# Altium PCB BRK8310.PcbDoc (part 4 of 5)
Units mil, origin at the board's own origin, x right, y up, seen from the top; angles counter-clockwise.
Board outline 6600.39 x 4492.13 mil, 4 copper layers (L1-Top, L2-GND, L3-GND, L4-BOT), stack 60.25 mil thick; 119 components, 266 nets, 1026 pads, 596 vias.
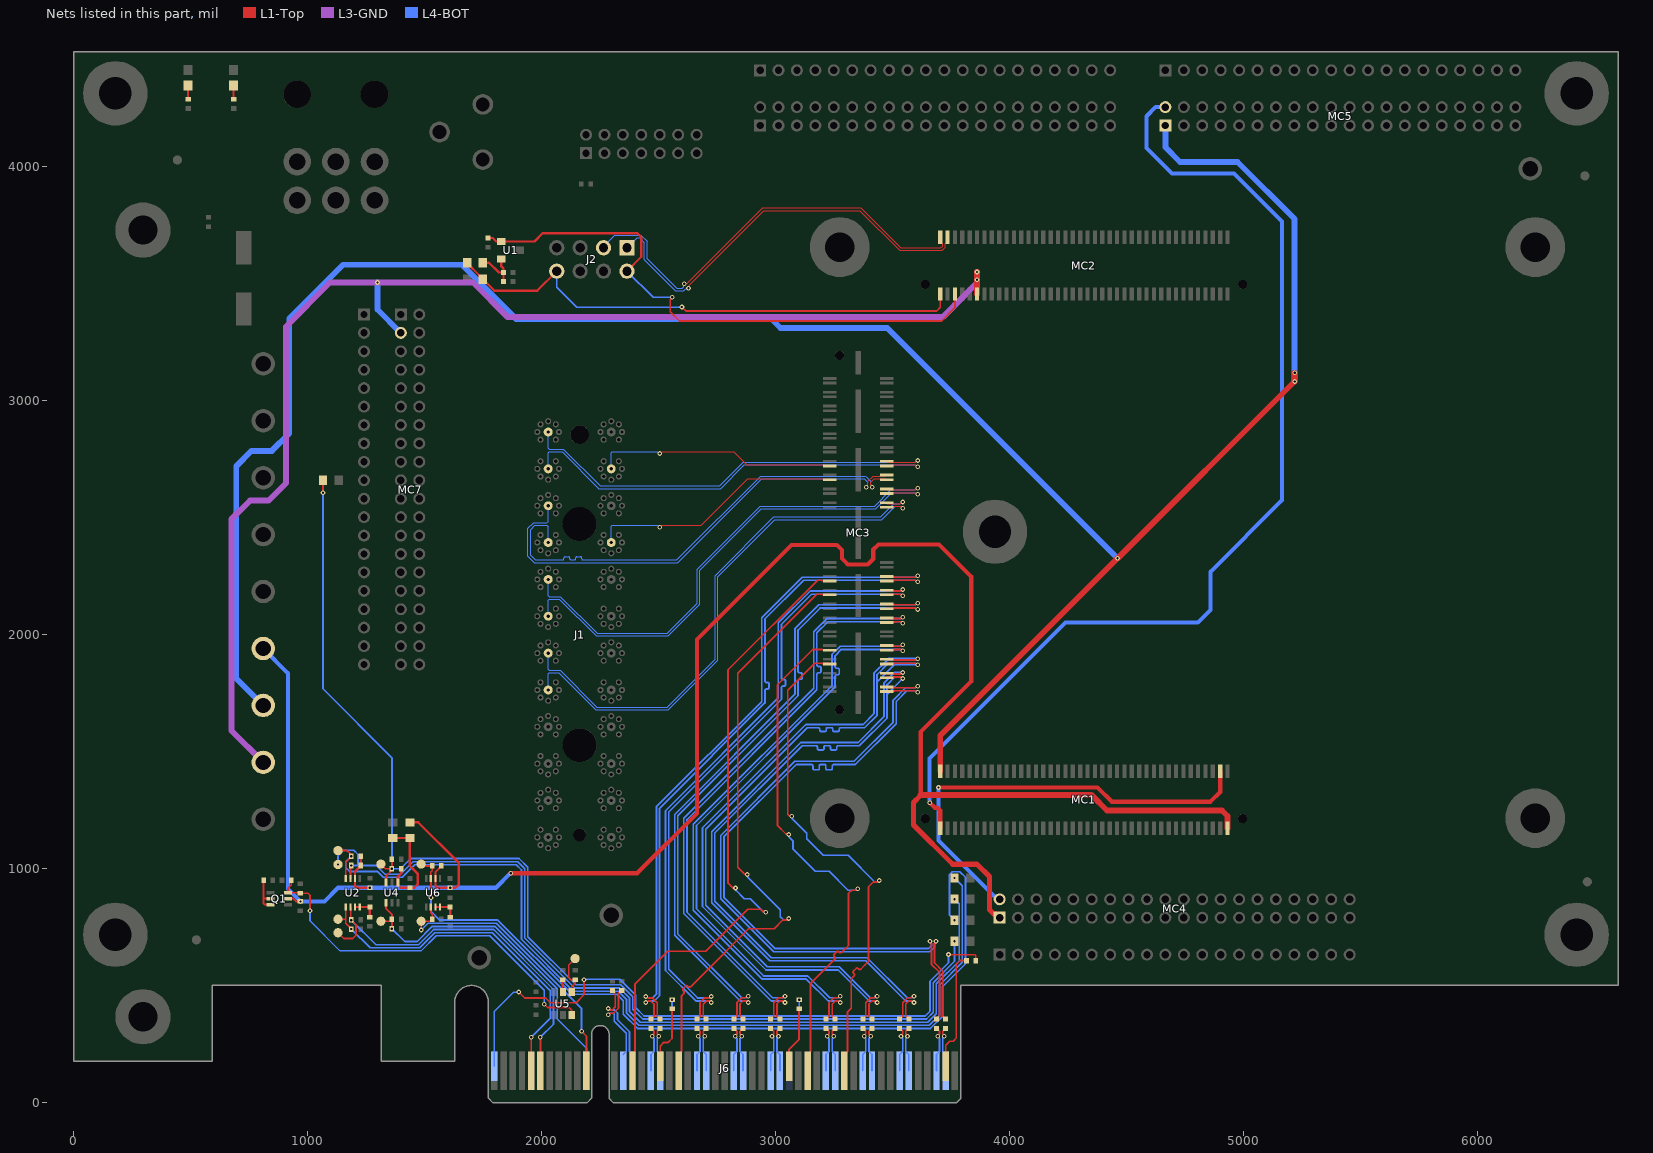
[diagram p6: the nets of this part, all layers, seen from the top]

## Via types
v1: diameter 20, hole 10, L1-Top to L4-BOT, tented both sides, 596 vias

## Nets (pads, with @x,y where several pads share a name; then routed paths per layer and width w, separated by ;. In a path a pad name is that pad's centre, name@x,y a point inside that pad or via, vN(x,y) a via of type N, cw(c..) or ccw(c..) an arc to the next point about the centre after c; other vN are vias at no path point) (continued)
MGT_RXP2_224: J6.B37 MC3.9 | length 2198.9
  L1-Top w7.5: v1(3068.1,1225.01) 3065.71,1227.41 3056.87,1227.41 3051.27,1233 3051.27,1764.37 3165.98,1879.08 3196.93,1879.08 3198.41,1877.6 3229.08,1877.6 MC3.9@3230.7,1875.98 ; J6.B37@3293.3,137.79 3293.3,206.69 3306.23,219.63 3306.23,240.7 3306.23,386.89 3323.12,403.78 3323.12,531.3 3331.45,539.62 3334.1,542.27 ccw(c3328.79,547.57) 3334.1,552.88 3331.89,555.08 cw(c3335.78,558.97) 3331.89,562.86 3343.56,574.53 cw(c3347.45,570.64) 3351.34,574.53 3353.54,572.32 ccw(c3358.85,577.62) 3364.15,572.32 3381.47,589.64 3396.44,604.61 3396.44,923.38 3417.16,944.1 3433.27,944.1 3439.52,950.35 v1(3442.91,950.35)
  L4-BOT w7.5: v1(3068.1,1225.01) 3070.49,1222.62 3070.49,1213.78 3132.67,1151.6 3132.67,1129.07 3203.66,1058.09 3309.84,1058.09 3423.83,944.1 3433.27,944.1 3439.52,950.35 v1(3442.91,950.35)
MGT_RXP2_225: J6.B19 MC3.29 | length 2643.1
  L1-Top w7.5: J6.B19@2584.64,137.79 2584.64,206.69 2597.57,219.63 2597.57,240.7 2597.57,458.1 2603.69,464.22 2606.35,466.87 ccw(c2601.04,472.17) 2606.35,477.48 2603.69,480.14 cw(c2607.57,484.03) 2603.69,487.92 2615.35,499.58 cw(c2619.24,495.69) 2623.13,499.58 2625.79,496.92 ccw(c2631.1,502.23) 2636.4,496.92 2687.36,547.88 2883.68,744.21 2992.94,744.21 3030.52,781.79 3050.72,781.79 3055.11,786.19 v1(3055.11,788.04) ; v1(2877.83,976.14) 2875.44,978.54 2866.6,978.54 2865.46,979.68 2837.44,1007.69 2837.44,1836.85 3174.94,2174.35 3196.93,2174.35 3198.41,2172.88 3229.08,2172.88 MC3.29@3230.7,2171.26
  L4-BOT w7.5: v1(2877.83,976.14) 2880.22,973.75 2880.22,964.91 3019.5,825.64 3019.5,796.16 3033.86,781.79 3045.48,781.79 3051.73,788.04 v1(3055.11,788.04)
MGT_RXP2_226: J1.B09 MC3.49 | length 1095
  L1-Top w5.25: v1(2504.63,2460.52) 2507.71,2460.52 2515.08,2467.89 2680.63,2467.89 2880.34,2667.6 3201.71,2667.6 3202.64,2666.66 3227.42,2666.66 MC3.49@3230.7,2663.38
  L4-BOT w5.25: J1.B09@2296.96,2394.78 2296.96,2463.74 2301.11,2467.89 2420.93,2467.89 2494.18,2467.89 2501.56,2460.52 v1(2504.63,2460.52)
MGT_RXP3_224: J6.B33 MC3.13 | length 2274
  L1-Top w7.5: v1(3055.22,1146.98) 3052.82,1149.38 3043.99,1149.38 3007.08,1186.28 3007.08,1785.87 3159.33,1938.13 3196.93,1938.13 3198.41,1936.66 3229.08,1936.66 MC3.13@3230.7,1935.04 ; J6.B33@3135.82,137.79 3135.82,206.69 3148.75,219.63 3148.75,510.61 3249.16,611.02 3251.81,613.67 ccw(c3246.51,618.97) 3251.81,624.27 3249.15,626.94 cw(c3253.04,630.82) 3249.15,634.71 3260.82,646.38 cw(c3264.71,642.49) 3268.59,646.38 3271.26,643.72 ccw(c3276.56,649.02) 3281.86,643.72 3297.2,659.06 3311.02,672.87 3311.02,895.49 3324.69,909.17 3344.41,909.17 3350.39,915.15 v1(3350.39,915.42)
  L4-BOT w7.5: v1(3055.22,1146.98) 3057.61,1144.59 3057.61,1135.75 3073.29,1120.07 3073.29,1085.56 3169.1,989.75 3228.25,989.75 3308.83,909.17 3340.75,909.17 3347,915.42 v1(3350.39,915.42)
MGT_RXP3_225: J6.B14 MC3.33 | length 2795.5
  L1-Top w7.5: J6.B14@2387.79,137.79 2387.79,206.69 2398.91,217.81 2398.91,508.47 2538.58,648.14 2700.54,648.14 2880.48,828.08 2935.88,828.08 2946.43,817.53 2955.27,817.53 v1(2957.66,815.14) ; v1(2828.19,918.18) 2827.8,917.79 2818.89,917.79 2795.42,941.26 2795.42,1849.99 3178.84,2233.41 3196.93,2233.41 3198.41,2231.93 3229.08,2231.93 MC3.33@3230.7,2230.31
  L4-BOT w7.5: v1(2828.19,918.18) 2830.58,915.79 2830.58,907.61 2865.42,872.76 2891.19,872.76 2946.43,817.53 2955.27,817.53 v1(2957.66,815.14)
MGT_RXP3_226: J1.B11 MC3.53 | length 1035.6
  L1-Top w5.25: v1(2504.63,2775.48) 2507.71,2775.48 2515.08,2782.85 2820.78,2782.85 2876.97,2726.66 3201.71,2726.66 3202.64,2725.72 3227.42,2725.72 MC3.53@3230.7,2722.44
  L4-BOT w5.25: J1.B11@2296.96,2709.74 2296.96,2778.7 2301.11,2782.85 2420.93,2782.85 2494.18,2782.85 2501.56,2775.48 v1(2504.63,2775.48)
MGT_TXN0_224: C30.2 MC3.4 | length 2965.2
  L1-Top w7.5: MC3.4@3474.01,1777.56 3476.16,1775.4 3506.84,1775.4 3507.77,1774.47 3596.66,1774.47 3602.91,1780.72 v1(3606.29,1780.72) ; v1(3685.1,690.4) 3685.1,687.02 3678.85,680.77 3678.85,597.93 3713.44,563.35 3713.44,369.54 3717.83,365.15 3720.28,365.15 C30.2@3726.37,359.05
  L4-BOT w7.5: v1(3606.29,1780.72) 3602.91,1780.72 3596.66,1774.47 3554.58,1774.47 3501.34,1721.23 3501.34,1626.46 3334.53,1459.65 3081.8,1459.65 2765,1142.84 2765,872.82 2991.87,645.95 3658.42,645.95 3678.85,666.38 3678.85,680.77 3685.1,687.02 v1(3685.1,690.4)
MGT_TXN0_225: C20.2 MC3.24 | length 2617.4
  L1-Top w7.5: C20.2@3017.71,359.05 3011.22,365.54 3009.17,365.54 3004.77,369.93 3004.77,386.56 3004.77,422.67 3017.54,435.43 3029.73,435.43 3035.98,429.18 v1(3039.36,429.18) ; MC3.24@3474.01,2072.83 3476.16,2070.68 3506.84,2070.68 3507.77,2069.74 3533.67,2069.74 3539.92,2075.99 v1(3543.3,2075.99)
  L4-BOT w7.5: v1(3039.36,429.18) 3035.98,429.18 3029.73,435.43 2980.67,435.43 2606.93,809.17 2606.93,1216.44 3162.18,1771.68 3162.18,2014.26 3217.65,2069.74 3533.67,2069.74 3539.92,2075.99 v1(3543.3,2075.99)
MGT_TXN0_226: J1.A06 MC3.44 | length 2298.2
  L1-Top w5.25: MC3.44@3474.01,2564.96 3477.29,2561.68 3502.06,2561.68 3503,2560.74 3512.13,2560.74 3532.85,2560.74 3540.22,2568.12 v1(3543.3,2568.12)
  L4-BOT w5.25: J1.A06@2027.27,1922.33 2027.27,1853.37 2031.42,1849.22 2077.99,1849.22 2235.64,1691.58 2535.78,1691.58 2610.71,1766.51 2740.74,1896.54 2740.74,2253.42 2991.69,2504.37 3448.81,2504.37 3505.18,2560.74 3532.85,2560.74 3540.22,2568.12 v1(3543.3,2568.12)
MGT_TXN1_224: C26.2 MC3.8 | length 2753.4
  L1-Top w7.5: MC3.8@3474.01,1836.61 3476.16,1834.46 3506.84,1834.46 3507.77,1833.52 3533.67,1833.52 3539.92,1839.77 v1(3543.3,1839.77) ; C26.2@3568.89,359.05 3562.4,365.54 3560.35,365.54 3555.95,369.93 3555.95,386.56 3555.95,422.67 3568.72,435.43 3580.91,435.43 3587.16,429.18 v1(3590.54,429.18)
  L4-BOT w7.5: v1(3543.3,1839.77) v1@3539.92,1839.77 ; v1(3590.54,429.18) 3587.16,429.18 3580.91,435.43 3555.96,435.43 3384.45,606.95 2974.62,606.95 2726,855.57 2726,1159 3107.36,1540.35 3352,1540.35 3462.34,1650.69 3462.34,1746.31 3462.34,1793.43 3502.43,1833.52 ; 3502.43,1833.52 3508.68,1839.77 v1@3539.92,1839.77 ; 3502.43,1833.52 3533.67,1833.52 v1@3539.92,1839.77
MGT_TXN1_225: C18.2 MC3.28 | length 2774.3
  L1-Top w7.5: C18.2@2860.23,359.05 2853.74,365.54 2851.69,365.54 2847.29,369.93 2847.29,386.56 2847.29,422.67 2860.06,435.43 2872.25,435.43 2878.5,429.18 v1(2881.88,429.18) ; MC3.28@3474.01,2131.89 3476.16,2129.73 3506.84,2129.73 3507.77,2128.8 3596.66,2128.8 3602.91,2135.05 v1(3606.29,2135.05)
  L4-BOT w7.5: v1(2881.88,429.18) 2878.5,429.18 2872.25,435.43 2848.81,435.43 2567.93,716.31 2567.93,1232.59 3081.97,1746.63 3081.97,2026.83 3183.94,2128.8 3596.66,2128.8 3602.91,2135.05 v1(3606.29,2135.05)
MGT_TXN1_226: J1.A08 MC3.48 | length 2194
  L1-Top w5.25: MC3.48@3474.01,2624.01 3477.29,2620.73 3502.06,2620.73 3503,2619.8 3595.84,2619.8 3603.22,2627.17 v1(3606.29,2627.17)
  L4-BOT w5.25: J1.A08@2027.27,2237.3 2027.27,2168.33 2031.42,2164.18 2079.67,2164.18 2236.8,2007.04 2535.62,2007.04 2664.03,2135.45 2664.03,2281.07 2933.44,2550.48 3422.14,2550.48 3491.46,2619.8 3595.84,2619.8 3603.22,2627.17 v1(3606.29,2627.17)
MGT_TXN2_224: C24.2 MC3.12 | length 2950.7
  L1-Top w7.5: C24.2@3411.41,359.05 3404.92,365.54 3402.87,365.54 3398.47,369.93 3398.47,386.56 3398.47,422.67 3411.24,435.43 3423.43,435.43 3429.68,429.18 v1(3433.06,429.18) ; MC3.12@3474.01,1895.67 3476.16,1893.51 3506.84,1893.51 3507.77,1892.58 3596.66,1892.58 3602.91,1898.83 v1(3606.29,1898.83)
  L4-BOT w7.5: v1(3433.06,429.18) 3429.68,429.18 3423.43,435.43 3398.97,435.43 3266.45,567.95 2958.47,567.95 2687,839.41 2687,1175.15 3128.97,1617.13 3373.62,1617.13 3419.56,1663.07 3419.56,1800.22 3419.56,1836.3 3475.84,1892.58 ; v1(3606.29,1898.83) v1@3602.91,1898.83 ; 3475.84,1892.58 3482.09,1898.83 v1@3602.91,1898.83 ; 3475.84,1892.58 3596.66,1892.58 v1@3602.91,1898.83
MGT_TXN2_225: C16.2 MC3.32 | length 2714.7
  L1-Top w7.5: C16.2@2702.75,358.66 2696.26,365.15 2694.21,365.15 2689.81,369.54 2689.81,386.17 2689.81,422.28 2702.58,435.04 2714.77,435.04 2721.02,428.79 v1(2724.4,428.79) ; MC3.32@3474.01,2190.94 3476.16,2188.79 3506.84,2188.79 3507.77,2187.85 3533.67,2187.85 3539.92,2194.1 v1(3543.3,2194.1)
  L4-BOT w7.5: v1(2724.4,428.79) 2721.02,428.79 2714.77,435.04 2659.76,435.04 2528.93,565.87 2528.93,1248.75 3011.11,1730.92 3011.11,2051.57 3147.38,2187.85 3533.67,2187.85 3539.92,2194.1 v1(3543.3,2194.1)
MGT_TXN2_226: J1.A10 MC3.52 | length 2048.7
  L1-Top w5.25: v1(3386.58,2631) 3386.58,2634.05 3393.95,2641.42 3393.95,2656.39 3416.41,2678.85 3437.59,2678.85 3445.01,2678.85 3445.95,2679.79 3470.73,2679.79 MC3.52@3474.01,2683.07
  L4-BOT w5.25: J1.A10@2027.27,2552.26 2027.27,2484.39 2022.03,2479.14 1964.69,2479.14 1940.52,2454.97 1940.52,2336.14 1967.44,2309.22 2581.12,2309.22 2939.49,2667.6 3378.34,2667.6 3393.95,2651.99 3393.95,2641.45 3386.58,2634.07 v1(3386.58,2631)
MGT_TXN3_224: C22.2 MC3.16 | length 2635.8
  L1-Top w7.5: C22.2@3253.93,359.05 3247.44,365.54 3245.39,365.54 3240.99,369.93 3240.99,386.56 3240.99,422.67 3253.76,435.43 3265.95,435.43 3272.2,429.18 v1(3275.58,429.18) ; MC3.16@3474.01,1954.72 3476.16,1952.57 3506.84,1952.57 3507.77,1951.63 3533.67,1951.63 3539.92,1957.88 v1(3543.3,1957.88)
  L4-BOT w7.5: v1(3275.58,429.18) 3272.2,429.18 3265.95,435.43 3224.32,435.43 3130.8,528.95 2942.31,528.95 2647.63,823.63 2647.63,1190.94 3240.18,1783.48 3240.18,1916.7 3275.11,1951.63 3533.67,1951.63 3539.92,1957.88 v1(3543.3,1957.88)
MGT_TXN3_225: C14.2 MC3.36 | length 2861.5
  L1-Top w7.5: v1(2444.87,454.79) 2448.26,454.79 2453.01,450.04 2453.22,450.04 2454.72,448.54 2472.29,448.54 2492.96,427.87 2492.96,380.58 2492.96,369.54 2497.36,365.15 2499.41,365.15 C14.2@2505.9,358.66 ; MC3.36@3474.01,2250 3476.16,2247.84 3506.84,2247.84 3507.77,2246.91 3596.66,2246.91 3602.91,2253.16 v1(3606.29,2253.16)
  L4-BOT w7.5: v1(2444.87,454.79) 2448.26,454.79 2454.51,448.54 2474.12,448.54 2489.93,464.35 2489.93,1264.9 2940.24,1715.21 2940.24,2073.48 3113.67,2246.91 3128.94,2246.91 3596.66,2246.91 3602.91,2253.16 v1(3606.29,2253.16)
MGT_TXN3_226: J1.A12 MC3.56 | length 1897
  L1-Top w5.25: MC3.56@3474.01,2742.12 3477.29,2738.84 3502.06,2738.84 3503,2737.91 3595.84,2737.91 3603.22,2745.28 v1(3606.29,2745.28)
  L4-BOT w5.25: J1.A12@2027.27,2867.22 2027.27,2798.25 2031.42,2794.1 2091.32,2794.1 2248.79,2636.64 2760.25,2636.64 2861.52,2737.91 3595.84,2737.91 3603.22,2745.28 v1(3606.29,2745.28)
MGT_TXP0_224: C29.2 MC3.2 | length 2966.6
  L1-Top w7.5: MC3.2@3474.01,1757.87 3476.16,1760.03 3506.84,1760.03 3507.77,1760.97 3596.66,1760.97 3602.91,1754.72 v1(3606.29,1754.72) ; v1(3659.1,690.4) 3659.1,687.02 3665.35,680.77 3665.35,592.34 3699.94,557.76 3699.94,369.54 3695.54,365.15 3693.09,365.15 C29.2@3687,359.05
  L4-BOT w7.5: v1(3606.29,1754.72) 3602.91,1754.72 3596.66,1760.97 3560.17,1760.97 3514.84,1715.63 3514.84,1620.86 3340.12,1446.15 3283.46,1446.15 3248.83,1446.15 ccw(c3248.83,1438.65) 3241.33,1438.65 3241.33,1429.37 cw(c3235.83,1429.37) 3235.83,1423.87 3219.33,1423.87 cw(c3219.33,1429.37) 3213.83,1429.37 3213.83,1440.65 ccw(c3208.33,1440.65) 3208.33,1446.15 3191.83,1446.15 ccw(c3191.83,1440.65) 3186.33,1440.65 3186.33,1429.37 cw(c3180.83,1429.37) 3180.83,1423.87 3164.33,1423.87 cw(c3164.33,1429.37) 3158.83,1429.37 3158.83,1438.65 ccw(c3151.33,1438.65) 3151.33,1446.15 3120.08,1446.15 3087.39,1446.15 2778.5,1137.25 2778.5,878.41 2997.46,659.45 3652.83,659.45 3665.35,671.97 3665.35,680.77 3659.1,687.02 v1(3659.1,690.4)
MGT_TXP0_225: C19.2 MC3.22 | length 2618.3
  L1-Top w7.5: C19.2@2978.34,359.05 2984.82,365.54 2986.88,365.54 2991.27,369.93 2991.27,380.97 2991.27,428.26 3011.94,448.93 3029.52,448.93 3031.02,450.43 3031.23,450.43 3035.98,455.18 v1(3039.36,455.18) ; MC3.22@3474.01,2053.15 3476.16,2055.3 3506.84,2055.3 3507.77,2056.24 3533.67,2056.24 3539.92,2049.99 v1(3543.3,2049.99)
  L4-BOT w7.5: v1(3039.36,455.18) 3035.98,455.18 3029.73,448.93 2986.27,448.93 2620.43,814.76 2620.43,1210.85 3175.68,1766.09 3175.68,1799.21 3175.68,1830.46 cw(c3183.18,1830.46) 3183.18,1837.96 3187.41,1837.96 ccw(c3187.41,1843.46) 3192.91,1843.46 3192.91,1859.96 ccw(c3187.41,1859.96) 3187.41,1865.46 3183.18,1865.46 cw(c3183.18,1872.96) 3175.68,1872.96 3175.68,1905.51 3175.68,2008.67 3223.25,2056.24 3533.67,2056.24 3539.92,2049.99 v1(3543.3,2049.99)
MGT_TXP0_226: J1.A05 MC3.42 | length 2298.2
  L1-Top w5.25: MC3.42@3474.01,2545.27 3477.29,2548.55 3502.06,2548.55 3503,2549.49 3516.79,2549.49 3532.85,2549.49 3540.22,2542.12 v1(3543.3,2542.12)
  L4-BOT w5.25: J1.A05@2027.27,1764.85 2027.27,1833.82 2031.42,1837.97 2073.33,1837.97 2230.98,1680.33 2540.44,1680.33 2748.69,1888.59 2751.99,1891.88 2751.99,2248.76 2996.35,2493.12 3453.47,2493.12 3509.84,2549.49 3532.85,2549.49 3540.22,2542.12 v1(3543.3,2542.12)
MGT_TXP1_224: C25.2 MC3.6 | length 2838.8
  L1-Top w7.5: MC3.6@3474.01,1816.93 3476.16,1819.08 3506.84,1819.08 3507.77,1820.02 3533.67,1820.02 3539.92,1813.77 v1(3543.3,1813.77) ; C25.2@3529.52,359.05 3536.01,365.54 3538.06,365.54 3542.45,369.93 3542.45,380.97 3542.45,428.26 3563.13,448.93 3580.7,448.93 3582.2,450.43 3582.41,450.43 3587.16,455.18 v1(3590.54,455.18)
  L4-BOT w7.5: v1(3590.54,455.18) 3587.16,455.18 3580.91,448.93 3561.55,448.93 3390.04,620.45 2980.21,620.45 2739.5,861.16 2739.5,1153.41 3112.95,1526.85 3139.76,1526.85 3171.01,1526.85 cw(c3171.01,1519.35) 3178.51,1519.35 3178.51,1514.09 ccw(c3184.01,1514.09) 3184.01,1508.59 3200.51,1508.59 ccw(c3200.51,1514.09) 3206.01,1514.09 3206.01,1521.35 cw(c3211.51,1521.35) 3211.51,1526.85 3228.01,1526.85 cw(c3228.01,1521.35) 3233.51,1521.35 3233.51,1514.09 ccw(c3239.01,1514.09) 3239.01,1508.59 3255.51,1508.59 ccw(c3255.51,1514.09) 3261.01,1514.09 3261.01,1519.35 cw(c3268.51,1519.35) 3268.51,1526.85 3296.26,1526.85 3357.59,1526.85 3475.84,1645.1 3475.84,1746.31 ; 3475.84,1746.31 3475.84,1787.84 3508.02,1820.02 3533.67,1820.02 3539.92,1813.77 v1(3543.3,1813.77) 3475.84,1746.31
MGT_TXP1_225: C17.2 MC3.26 | length 2774.6
  L1-Top w7.5: C17.2@2820.86,359.05 2827.34,365.54 2829.4,365.54 2833.79,369.93 2833.79,380.97 2833.79,428.26 2854.46,448.93 2872.04,448.93 2873.54,450.43 2873.75,450.43 2878.5,455.18 v1(2881.88,455.18) ; MC3.26@3474.01,2112.2 3476.16,2114.36 3506.84,2114.36 3507.77,2115.3 3596.66,2115.3 3602.91,2109.05 v1(3606.29,2109.05)
  L4-BOT w7.5: v1(2881.88,455.18) 2878.5,455.18 2872.25,448.93 2854.4,448.93 2581.43,721.9 2581.43,1227 3095.47,1741.04 3095.47,1771.65 3095.47,1802.9 cw(c3102.97,1802.9) 3102.97,1810.4 3106.93,1810.4 ccw(c3106.93,1815.9) 3112.43,1815.9 3112.43,1832.4 ccw(c3106.93,1832.4) 3106.93,1837.9 3102.97,1837.9 cw(c3102.97,1845.4) 3095.47,1845.4 3095.47,1866.14 3095.47,2021.24 3189.53,2115.3 3596.66,2115.3 3602.91,2109.05 v1(3606.29,2109.05)
MGT_TXP1_226: J1.A07 MC3.46 | length 2194
  L1-Top w5.25: MC3.46@3474.01,2604.33 3477.29,2607.61 3502.06,2607.61 3503,2608.55 3595.84,2608.55 3603.22,2601.17 v1(3606.29,2601.17)
  L4-BOT w5.25: J1.A07@2027.27,2079.81 2027.27,2148.78 2031.42,2152.93 2075.01,2152.93 2232.14,1995.79 2540.28,1995.79 2675.28,2130.79 2675.28,2276.41 2938.1,2539.23 3426.8,2539.23 3496.12,2608.55 3595.84,2608.55 3603.22,2601.17 v1(3606.29,2601.17)
MGT_TXP2_224: C23.2 MC3.10 | length 3042.3
  L1-Top w7.5: C23.2@3372.04,359.05 3378.53,365.54 3380.58,365.54 3384.97,369.93 3384.97,380.97 3384.97,428.26 3405.65,448.93 3423.22,448.93 3424.72,450.43 3424.93,450.43 3429.68,455.18 v1(3433.06,455.18) ; MC3.10@3474.01,1875.98 3476.16,1878.14 3506.84,1878.14 3507.77,1879.08 3596.66,1879.08 3602.91,1872.83 v1(3606.29,1872.83)
  L4-BOT w7.5: v1(3433.06,455.18) 3429.68,455.18 3423.43,448.93 3404.56,448.93 3272.04,581.45 2964.06,581.45 2700.5,845.01 2700.5,1169.56 3134.56,1603.63 3149.61,1603.63 3180.86,1603.63 cw(c3180.86,1596.13) 3188.36,1596.13 3188.36,1593.06 ccw(c3193.86,1593.06) 3193.86,1587.56 3210.36,1587.56 ccw(c3210.36,1593.06) 3215.86,1593.06 3215.86,1598.13 cw(c3221.36,1598.13) 3221.36,1603.63 3237.86,1603.63 cw(c3237.86,1598.13) 3243.36,1598.13 3243.36,1593.06 ccw(c3248.86,1593.06) 3248.86,1587.56 3265.36,1587.56 ccw(c3265.36,1593.06) 3270.86,1593.06 3270.86,1596.13 cw(c3278.36,1596.13) 3278.36,1603.63 3297.98,1603.63 3379.21,1603.63 3433.06,1657.48 3433.06,1800.22 ; v1(3606.29,1872.83) v1@3602.91,1872.83 ; 3433.06,1800.22 3433.06,1830.71 3481.43,1879.08 3596.66,1879.08 v1@3602.91,1872.83 ; 3433.06,1800.22 3505.67,1872.83 v1@3602.91,1872.83
MGT_TXP2_225: C15.2 MC3.30 | length 2715.1
  L1-Top w7.5: C15.2@2663.38,358.66 2669.86,365.15 2671.92,365.15 2676.31,369.54 2676.31,380.58 2676.31,427.87 2696.98,448.54 2714.56,448.54 2716.06,450.04 2716.27,450.04 2721.02,454.79 v1(2724.4,454.79) ; MC3.30@3474.01,2171.26 3476.16,2173.41 3506.84,2173.41 3507.77,2174.35 3533.67,2174.35 3539.92,2168.1 v1(3543.3,2168.1)
  L4-BOT w7.5: v1(2724.4,454.79) 2721.02,454.79 2714.77,448.54 2665.35,448.54 2542.43,571.46 2542.43,1243.16 3024.61,1725.33 3024.61,1742.88 3024.61,1774.13 cw(c3032.11,1774.13) 3032.11,1781.63 3036.06,1781.63 ccw(c3036.06,1787.13) 3041.56,1787.13 3041.56,1803.63 ccw(c3036.06,1803.63) 3036.06,1809.13 3032.11,1809.13 cw(c3032.11,1816.63) 3024.61,1816.63 3024.61,1842.23 3024.61,2045.98 3152.98,2174.35 3533.67,2174.35 3539.92,2168.1 v1(3543.3,2168.1)
MGT_TXP2_226: J1.A09 MC3.50 | length 2048.7
  L1-Top w5.25: v1(3412.58,2631) 3412.58,2634.05 3405.2,2641.42 3405.2,2651.73 3421.07,2667.6 3432.93,2667.6 3445.01,2667.6 3445.95,2666.66 3470.73,2666.66 MC3.50@3474.01,2663.38
  L4-BOT w5.25: J1.A09@2027.27,2394.78 2027.27,2462.65 2022.03,2467.89 1969.35,2467.89 1951.77,2450.31 1951.77,2340.8 1972.1,2320.47 2080.71,2320.47 2089.23,2320.47 ccw(c2089.23,2325.72) 2094.48,2325.72 2094.48,2328.7 cw(c2099.53,2328.7) 2099.53,2333.75 2114.68,2333.75 cw(c2114.68,2328.7) 2119.73,2328.7 2119.73,2325.52 ccw(c2124.78,2325.52) 2124.78,2320.47 2139.93,2320.47 ccw(c2139.93,2325.52) 2144.98,2325.52 2144.98,2329.54 cw(c2150.03,2329.54) 2150.03,2334.59 2165.18,2334.59 cw(c2165.18,2329.54) 2170.23,2329.54 2170.23,2325.72 ccw(c2175.48,2325.72) 2175.48,2320.47 2203.36,2320.47 2576.46,2320.47 2934.83,2678.85 3383,2678.85 3386.29,2675.56 3405.2,2656.65 3405.2,2641.45 3412.58,2634.07 v1(3412.58,2631)
MGT_TXP3_224: C21.2 MC3.14 | length 2636.9
  L1-Top w7.5: C21.2@3214.56,359.05 3221.05,365.54 3223.1,365.54 3227.49,369.93 3227.49,380.97 3227.49,428.26 3248.17,448.93 3265.74,448.93 3267.24,450.43 3267.45,450.43 3272.2,455.18 v1(3275.58,455.18) ; MC3.14@3474.01,1935.04 3476.16,1937.19 3506.84,1937.19 3507.77,1938.13 3533.67,1938.13 3539.92,1931.88 v1(3543.3,1931.88)
  L4-BOT w7.5: v1(3275.58,455.18) 3272.2,455.18 3265.95,448.93 3229.91,448.93 3136.4,542.45 2947.9,542.45 2661.13,829.22 2661.13,1185.35 3253.68,1777.89 3253.68,1791.34 3253.68,1822.59 cw(c3261.18,1822.59) 3261.18,1830.09 3265.47,1830.09 ccw(c3265.47,1835.59) 3270.97,1835.59 3270.97,1852.09 ccw(c3265.47,1852.09) 3265.47,1857.59 3261.18,1857.59 cw(c3261.18,1865.09) 3253.68,1865.09 3253.68,1895.67 3253.68,1911.11 3280.7,1938.13 3533.67,1938.13 3539.92,1931.88 v1(3543.3,1931.88)
MGT_TXP3_225: C13.2 MC3.34 | length 2862.4
  L1-Top w7.5: v1(2444.87,428.79) 2448.26,428.79 2454.51,435.04 2466.7,435.04 2479.46,422.28 2479.46,386.17 2479.46,369.54 2475.07,365.15 2473.01,365.15 C13.2@2466.53,358.66 ; MC3.34@3474.01,2230.31 3476.16,2232.47 3506.84,2232.47 3507.77,2233.41 3596.66,2233.41 3602.91,2227.16 v1(3606.29,2227.16)
  L4-BOT w7.5: v1(2444.87,428.79) 2448.26,428.79 2454.51,435.04 2479.72,435.04 2503.43,458.76 2503.43,1259.31 2953.74,1709.62 2953.74,1730.32 2953.74,1761.57 cw(c2961.24,1761.57) 2961.24,1769.07 2965.48,1769.07 ccw(c2965.48,1774.57) 2970.98,1774.57 2970.98,1791.07 ccw(c2965.48,1791.07) 2965.48,1796.57 2961.24,1796.57 cw(c2961.24,1804.07) 2953.74,1804.07 2953.74,1829.72 2953.74,2067.88 3119.26,2233.41 3596.66,2233.41 3602.91,2227.16 v1(3606.29,2227.16)
MGT_TXP3_226: J1.A11 MC3.54 | length 1897
  L1-Top w5.25: MC3.54@3474.01,2722.44 3477.29,2725.72 3502.06,2725.72 3503,2726.66 3595.84,2726.66 3603.22,2719.28 v1(3606.29,2719.28)
  L4-BOT w5.25: J1.A11@2027.27,2709.74 2027.27,2778.7 2031.42,2782.85 2086.66,2782.85 2244.13,2625.39 2764.91,2625.39 2866.18,2726.66 3595.84,2726.66 3603.22,2719.28 v1(3606.29,2719.28)
NetC2_2: C2.2 C3.1 R5.1 U1.2 | length 207.1
  L1-Top w10: R5.1@1747.73,3591.06 1774.38,3591.06 1816.48,3548.96 C3.1@1836.45,3548.96 ; U1.2@1827.16,3606.81 1827.16,3575.31 1836.45,3566.02 C3.1@1836.45,3548.96 ; C2.2@1836.45,3509.73 C3.1@1836.45,3548.96
NetC10_2: C10.2 R13.1 U2.7 U2.8 | length 106.1
  L1-Top w10: U2.7@1201.91,837.38 1201.91,837.26 1201.99,837.19 1264.71,837.19 C10.2@1264.9,836.99 R13.1@1264.9,794.08
NetC11_2: C11.2 R1.1 R2.1 R20.2 U4.1 | length 455.5
  L1-Top w10: R2.1@1363.39,1131.85 R1.1@1436.16,1131.85 1436.16,1012.58 1470.47,978.27 1470.47,935.27 1454.47,919.27 C11.2@1436.16,919.27 1397.58,919.27 1384.98,931.87 U4.1@1384.98,941.71 1384.98,966.62 1398.76,980.4 R20.2@1398.76,1000.77
NetC28_2: C28.2 R23.1 U6.7 U6.8 | length 106.1
  L1-Top w10: U6.7@1545.42,837.38 1545.42,837.26 1545.49,837.19 1608.21,837.19 1608.41,836.99 C28.2@1608.41,836.59 R23.1@1608.41,794.08
NetD1_2: D1.2 R3.1 | length 59
  L1-Top w8: R3.1@488.36,4289.37 D1.2@488.36,4348.38
NetD2_2: D2.2 R4.1 | length 59.4
  L1-Top w8: D2.2@681.88,4348.38 682.87,4347.39 R4.1@682.87,4289.37
NetJ6_B17: J6.B17 R27.1 | length 275.9
  L1-Top w7.5: J6.B17@2505.9,157.48 2505.9,242.76 2521.71,258.56 2540.05,258.56 2556.62,275.13 R27.1@2556.62,401.57
NetJ6_B31: J6.B31 R28.1 | length 262.8
  L1-Top w7.5: J6.B31@3057.08,157.48 3057.08,228.89 3099.84,271.65 R28.1@3099.84,401.57 R28.1@3099.84,402.6
NetJ6_B48: J6.B48 R29.1 | length 512.7
  L1-Top w7: J6.B48@3726.37,157.48 3726.37,246.4 3743.28,263.3 3758.13,263.3 3771.96,277.13 3771.96,593.12 3787.11,608.27 R29.1@3815.15,608.27
NetQ1_5: Q1.5 Q1.6 R30.1 | length 160.6
  L1-Top w8: R30.1@811.07,951.56 811.07,872.82 ; Q1.6@840.6,847.23 815.75,847.23 811.07,851.91 811.07,872.82 ; Q1.5@840.6,872.82 811.07,872.82
NetR18_1: R18.1 TP21.1 U5.4 | length 182.8
  L1-Top w7: U5.4@2127.94,473.62 2127.94,495.7 2142.43,510.18 R18.1@2142.43,526.77 2124.02,526.77 2114.92,535.88 2114.92,589.34 TP21.1@2142.43,616.85
NetR24_2: R24.2 U5.5 | length 54
  L1-Top w8: R24.2@2088.57,526.77 2088.57,475.59 U5.5@2090.54,473.62
PCIE_PERST_B_3V3: J6.A11 R21.1 R22.2 TP14.1 U4.4 | length 1439
  L1-Top w7.5: TP14.1@1312.15,776.36 1353.3,776.36 R21.1@1359.39,782.45 ; U4.4@1333.8,855.1 1333.8,831.29 1359.39,805.7 R21.1@1359.39,784.23 R21.1@1359.39,782.45 ; v1(1359.39,744.86) R21.1@1359.39,782.45
  L4-BOT w7.5: v1(1359.39,744.86) 1414.55,689.7 1467.33,689.7 1531.91,754.28 1799.56,754.28 2065.69,488.15 2065.69,358.36 2190.94,233.12 J6.A11@2190.94,137.79
PCIE_PERST_B_VIO: R7.1 R8.1 R12.2 R20.1 TP13.1 U4.3 | length 5120.7
  L1-Top w7.5: v1(1064.96,2607.51) R7.1@1064.96,2660.94 ; TP13.1@1312.15,1020.45 1331.83,1000.77 v1(1359.39,1000.77) ; U4.3@1333.8,941.71 1333.8,968.24 1353.3,987.74 1353.3,994.68 v1(1359.39,1000.77) ; R12.2@1359.39,1040.98 v1(1359.39,1000.77)
  L4-BOT w7.5: v1(1064.96,2607.51) 1064.96,1769.68 1359.39,1475.25 v1(1359.39,1000.77) 1395.89,1000.77 1439.53,1044.4 1902.72,1044.4 1940.38,1006.75 1940.38,710.41 2146.27,504.52 2337.81,504.52 2388.76,453.58 2388.76,400.96 2431.45,358.27 3644.19,358.27 3672.63,386.71 3672.63,514.21 3764.06,605.63 v1(3764.06,690.4)
PCIE_PRSNT1_B: J6.A1 R27.2 R28.2 R29.2 | length 2885.6
  L1-Top w7: v1(1901.57,473.58) 1926.61,448.54 2016.79,448.54 2037.46,427.87 2146.73,427.87 2180.61,461.74 v1(2180.61,526.74) ; v1(3738.18,633.86) 3850.39,633.86 3854.52,629.73 R29.2@3854.52,608.27
  L4-BOT w7: J6.A1@1797.24,157.48 1797.24,390.55 1880.27,473.58 v1(1901.57,473.58) ; v1(2180.61,526.74) 2182.06,528.19 2333.65,528.19 2402.01,459.84 2402.01,406.45 2436.94,371.52 2556.62,371.52 ; v1(2556.62,440.94) 2556.62,371.52 ; v1(3099.84,440.94) 3099.84,371.52 ; v1(3738.18,633.86) 3738.18,598.5 3659.38,519.69 3659.38,392.2 3638.7,371.52 3099.84,371.52 ; 2556.62,371.52 3099.84,371.52
PCIE_REFCLKN_C: C8.1 J6.A14 | length 442.2
  L1-Top w7.5: v1(2283.67,403.25) 2287.05,403.25 2293.3,397 2300.91,397 2314.41,410.5 2314.41,468.5 ; C8.1@2302.25,480.07 2308.74,473.58 C8.1@2309.33,473.58 ; C8.1@2309.33,473.58 2310.01,473.58 2314.41,469.19 2314.41,468.5 ; C8.1@2309.33,473.58 2314.41,468.5
  L4-BOT w7.5: v1(2283.67,403.25) 2284.1,403.25 2290.35,397 2310.7,397 2323.51,384.19 2323.51,355.07 2374.85,303.73 2374.85,219.63 2387.79,206.69 J6.A14@2387.79,137.79
PCIE_REFCLKP_C: C7.1 J6.A13 | length 375
  L1-Top w7.5: v1(2283.67,377.25) 2287.05,377.25 2293.3,383.5 2306.5,383.5 2327.91,404.91 2327.91,468.41 ; C7.1@2341.62,480.07 2335.13,473.58 C7.1@2333.08,473.58 ; 2327.91,468.41 2327.91,469.19 2332.3,473.58 C7.1@2333.08,473.58 ; 2327.91,468.41 C7.1@2333.08,473.58
  L4-BOT w7.5: v1(2283.67,377.25) 2284.1,377.25 2290.35,383.5 2305.11,383.5 2310.01,378.6 2310.01,349.48 2361.35,298.14 2361.35,219.63 J6.A13@2348.42,206.69
PCIE_RX0N_C: C14.1 J6.A17 | length 197.6
  L1-Top w7.5: v1(2499.99,285.27) 2499.99,287.89 2492.96,294.92 2492.96,306.16 2498.82,312.02 2499.41,312.02 C14.1@2505.9,318.5
  L4-BOT w7.5: v1(2499.99,285.27) 2499.99,282.66 2492.96,275.63 2492.96,219.63 2505.9,206.69 J6.A17@2505.9,137.79
PCIE_RX0P_C: C13.1 J6.A16 | length 197.6
  L1-Top w7.5: C13.1@2466.53,318.5 2473.01,312.02 2473.6,312.02 2479.46,306.16 2479.46,294.92 2472.43,287.89 v1(2472.43,285.27)
  L4-BOT w7.5: J6.A16@2466.53,137.79 2466.53,206.69 2479.46,219.63 2479.46,275.63 2472.43,282.66 v1(2472.43,285.27)
PCIE_RX1N_C: C16.1 J6.A22 | length 197.6
  L1-Top w7.5: v1(2696.84,285.27) 2696.84,287.89 2689.81,294.92 2689.81,306.16 2695.67,312.02 2696.26,312.02 C16.1@2702.75,318.5
  L4-BOT w7.5: v1(2696.84,285.27) 2696.84,282.66 2689.81,275.63 2689.81,219.63 2702.75,206.69 J6.A22@2702.75,137.79
PCIE_RX1P_C: C15.1 J6.A21 | length 197.6
  L1-Top w7.5: C15.1@2663.38,318.5 2669.86,312.02 2670.45,312.02 2676.31,306.16 2676.31,294.92 2669.28,287.89 v1(2669.28,285.27)
  L4-BOT w7.5: J6.A21@2663.38,137.79 2663.38,206.69 2676.31,219.63 2676.31,275.63 2669.28,282.66 v1(2669.28,285.27)
PCIE_RX2N_C: C18.1 J6.A26 | length 197.6
  L1-Top w7.5: v1(2854.32,285.27) 2854.32,287.89 2847.29,294.92 2847.29,306.16 2853.15,312.02 2853.74,312.02 C18.1@2860.23,318.5
  L4-BOT w7.5: v1(2854.32,285.27) 2854.32,282.66 2847.29,275.63 2847.29,219.63 2860.23,206.69 J6.A26@2860.23,137.79
PCIE_RX2P_C: C17.1 J6.A25 | length 197.6
  L1-Top w7.5: C17.1@2820.86,318.5 2827.34,312.02 2827.94,312.02 2833.79,306.16 2833.79,294.92 2826.76,287.89 v1(2826.76,285.27)
  L4-BOT w7.5: J6.A25@2820.86,137.79 2820.86,206.69 2833.79,219.63 2833.79,275.63 2826.76,282.66 v1(2826.76,285.27)
PCIE_RX3N_C: C20.1 J6.A30 | length 197.6
  L1-Top w7.5: v1(3011.8,285.27) 3011.8,287.89 3004.77,294.92 3004.77,306.16 3010.63,312.02 3011.22,312.02 C20.1@3017.71,318.5
  L4-BOT w7.5: v1(3011.8,285.27) 3011.8,282.66 3004.77,275.63 3004.77,219.63 3017.71,206.69 J6.A30@3017.71,137.79
PCIE_RX3P_C: C19.1 J6.A29 | length 197.6
  L1-Top w7.5: C19.1@2978.34,318.5 2984.82,312.02 2985.42,312.02 2991.27,306.16 2991.27,294.92 2984.24,287.89 v1(2984.24,285.27)
  L4-BOT w7.5: J6.A29@2978.34,137.79 2978.34,206.69 2991.27,219.63 2991.27,275.63 2984.24,282.66 v1(2984.24,285.27)
PCIE_RX4N_C: C22.1 J6.A36 | length 197.6
  L1-Top w7.5: v1(3248.02,285.27) 3248.02,287.89 3240.99,294.92 3240.99,306.16 3246.85,312.02 3247.44,312.02 C22.1@3253.93,318.5
  L4-BOT w7.5: v1(3248.02,285.27) 3248.02,282.66 3240.99,275.63 3240.99,219.63 3253.93,206.69 J6.A36@3253.93,137.79
PCIE_RX4P_C: C21.1 J6.A35 | length 197.6
  L1-Top w7.5: C21.1@3214.56,318.5 3221.05,312.02 3221.64,312.02 3227.49,306.16 3227.49,294.92 3220.46,287.89 v1(3220.46,285.27)
  L4-BOT w7.5: J6.A35@3214.56,137.79 3214.56,206.69 3227.49,219.63 3227.49,275.63 3220.46,282.66 v1(3220.46,285.27)
PCIE_RX5N_C: C24.1 J6.A40 | length 197.6
  L1-Top w7.5: v1(3405.5,285.27) 3405.5,287.89 3398.47,294.92 3398.47,306.16 3404.33,312.02 3404.92,312.02 C24.1@3411.41,318.5
  L4-BOT w7.5: v1(3405.5,285.27) 3405.5,282.66 3398.47,275.63 3398.47,219.63 3411.41,206.69 J6.A40@3411.41,137.79
PCIE_RX5P_C: C23.1 J6.A39 | length 197.6
  L1-Top w7.5: C23.1@3372.04,318.5 3378.53,312.02 3379.12,312.02 3384.97,306.16 3384.97,294.92 3377.94,287.89 v1(3377.94,285.27)
  L4-BOT w7.5: J6.A39@3372.04,137.79 3372.04,206.69 3384.97,219.63 3384.97,275.63 3377.94,282.66 v1(3377.94,285.27)
PCIE_RX6N_C: C26.1 J6.A44 | length 197.6
  L1-Top w7.5: v1(3562.98,285.27) 3562.98,287.89 3555.95,294.92 3555.95,306.16 3561.81,312.02 3562.4,312.02 C26.1@3568.89,318.5
  L4-BOT w7.5: v1(3562.98,285.27) 3562.98,282.66 3555.95,275.63 3555.95,219.63 3568.89,206.69 J6.A44@3568.89,137.79
PCIE_RX6P_C: C25.1 J6.A43 | length 197.6
  L1-Top w7.5: C25.1@3529.52,318.5 3536.01,312.02 3536.6,312.02 3542.45,306.16 3542.45,294.92 3535.43,287.89 v1(3535.43,285.27)
  L4-BOT w7.5: J6.A43@3529.52,137.79 3529.52,206.69 3542.45,219.63 3542.45,275.63 3535.43,282.66 v1(3535.43,285.27)
PCIE_RX7N_C: C30.1 J6.A48 | length 197.6
  L1-Top w7.5: v1(3720.46,285.27) 3720.46,287.89 3713.44,294.92 3713.44,306.16 3719.29,312.02 3719.88,312.02 C30.1@3726.37,318.5
  L4-BOT w7.5: v1(3720.46,285.27) 3720.46,282.66 3713.44,275.63 3713.44,219.63 3726.37,206.69 J6.A48@3726.37,137.79
PCIE_RX7P_C: C29.1 J6.A47 | length 197.6
  L1-Top w7.5: C29.1@3687,318.5 3693.49,312.02 3694.08,312.02 3699.94,306.16 3699.94,294.92 3692.91,287.89 v1(3692.91,285.27)
  L4-BOT w7.5: J6.A47@3687,137.79 3687,206.69 3699.94,219.63 3699.94,275.63 3692.91,282.66 v1(3692.91,285.27)
PCIE_SMCLK_3V3: J6.B5 R17.1 TP11.1 U2.5 | length 1525.2
  L1-Top w7.5: TP11.1@1129.01,785.03 1162.54,785.03 ; U2.5@1162.54,837.38 1162.54,785.03 ; v1(1186.16,742.89) 1186.16,744.86 1162.54,768.48 1162.54,785.03 ; J6.B5@1954.72,137.79 v1(1954.72,280.12)
  L4-BOT w7.5: v1(1186.16,742.89) 1266.36,662.7 1478.52,662.7 1543.09,727.28 1787.54,727.28 2036.02,478.8 2036.02,361.43 v1(1954.72,280.12)
PCIE_SMCLK_VIO: R11.1 R14.1 TP12.1 U2.4 | length 3960
  L1-Top w7.5: TP12.1@1129.01,1078.33 1167.89,1078.33 1180.07,1066.14 1180.07,1060.01 v1(1186.16,1053.92) 1186.16,1051.95 1162.54,1028.33 U2.4@1162.54,959.43
  L4-BOT w7.5: v1(1186.16,1053.92) 1162.54,1030.3 1162.54,1004.85 1178.12,989.27 1296.87,989.27 1322.27,963.88 1404.05,963.88 1457.57,1017.4 1891.54,1017.4 1913.38,995.56 1913.38,699.23 2135.08,477.52 2326.63,477.52 2361.76,442.4 2361.76,384.55 2386.45,359.86 2415.04,331.27 3655.37,331.27 3699.63,375.53 3699.63,503.02 3797.31,600.7 3797.31,928.13 v1(3764.26,961.18)
PCIE_SMDAT_3V3: J6.B6 R16.1 TP10.1 U2.6 | length 1633.8
  L1-Top w7.5: TP10.1@1129.01,727.15 1153.62,702.54 1191.79,702.54 1205.91,716.67 1205.91,760.55 1186.16,780.3 v1(1186.16,781.28) R16.1@1186.16,782.26 1183.4,785.03 1183.4,836.21 U2.6@1182.23,837.38 ; J6.B6@1994.09,137.79 v1(1994.09,280.27)
  L4-BOT w7.5: v1(1186.16,781.28) 1291.24,676.2 1472.92,676.2 1537.5,740.78 1793.97,740.78 2050.11,484.64 2050.11,336.3 v1(1994.09,280.27)
PCIE_SMDAT_VIO: R10.1 R15.1 TP9.1 U2.3 | length 3826.7
  L1-Top w7.5: U2.3@1182.23,959.43 1182.23,1010.61 v1(1186.16,1014.55)
  L4-BOT w7.5: v1(1129.01,1018.75) 1129.01,1056.19 1152.51,1079.68 1196.54,1079.68 1214.56,1061.66 1214.56,1014.55 ; v1(1186.16,1014.55) 1214.56,1014.55 ; v1(3764.26,870.92) 3783.81,851.37 3783.81,606.29 3686.13,508.61 3686.13,381.12 3649.78,344.77 2420.63,344.77 2375.26,390.14 2375.26,447.99 2332.22,491.02 2140.68,491.02 1926.88,704.82 1926.88,1001.16 1897.13,1030.9 1449.53,1030.9 1396,977.38 1329.8,977.38 1292.62,1014.55 1214.56,1014.55
PCIE_WAKE_B_3V3: J6.B11 R26.1 TP16.1 U6.6 | length 1266.8
  L1-Top w7.5: v1(1484.73,738.95) 1484.56,739.11 1484.56,776.19 TP16.1@1484.39,776.36 1525.54,776.36 1531.64,782.45 R26.1@1531.64,784.23 1531.64,806.42 1525.73,812.32 U6.6@1525.73,837.38 ; v1(2170.06,306.16) 2190.94,285.29 J6.B11@2190.94,137.79
  L4-BOT w7.5: v1(1484.73,738.95) 1513.56,767.78 1805.16,767.78 2170.06,402.87 v1(2170.06,306.16)
PCIE_WAKE_B_VIO: R9.1 R25.1 TP15.1 U6.3 | length 3618.2
  L1-Top w7.5: TP15.1@1484.39,1020.45 1490.49,1014.36 1502.95,1014.36 1504.72,1012.58 R25.1@1531.64,1012.58 1531.64,992.9 1525.73,986.99 U6.3@1525.73,959.43 1526.14,959.02 1526.14,877.62 v1(1526.54,877.22)
  L4-BOT w7.5: v1(1526.54,877.22) 1526.54,818.85 1564.12,781.28 1812.24,781.28 2129.49,464.02 2321.04,464.02 2348.26,436.81 2348.26,378.96 2409.45,317.77 3660.96,317.77 3713.13,369.93 3713.13,497.43 3810.81,595.11 3810.81,964.26 3787.11,987.95 3754.86,987.95 3742.86,975.95 3742.86,801.86 v1(3764.06,780.66)
VBATT: MC1.79 MC5.2 | length 4515.2
  L1-Top w18: v1(3657.66,1283.37) 3679.29,1261.74 3690.02,1261.74 3702.75,1249.02 MC1.79@3702.75,1173.82
  L4-BOT w18: v1(3657.66,1283.37) 3657.66,1464.57 3657.66,1471.88 4238.61,2052.83 4803.91,2052.83 4857.98,2106.9 4857.98,2269.66 5164.26,2575.95 5164.26,3766.44 4958.27,3972.44 4693.61,3972.44 4584.64,4081.42 4584.64,4216.91 4623.63,4255.9 MC5.2@4665.35,4255.9
VCCADC: C1.1 J2.2 MC2.75 U1.1 | length 2475.9
  L1-Top w7.5: v1(2557.09,3442.91) 2557.09,3440.26 2549.1,3432.27 2549.1,3381.06 2588.62,3341.54 3709.65,3341.54 3765.74,3397.63 3765.74,3456.68 MC2.75@3767.72,3458.66
  L1-Top w10: C1.1@1770.65,3696.77 1790.02,3696.77 1805.18,3681.61 U1.1@1827.16,3681.61 1968.45,3681.61 2003.37,3716.54 2408.98,3716.54 2425.34,3700.18 2425.34,3616.11 J2.2@2363.92,3554.69
  L4-BOT w7.5: J2.2@2363.92,3554.69 2475.7,3442.91 v1(2557.09,3442.91)
VIO1: C9.2 C27.2 MC1.1 MC4.1 Q1.2 R1.2 R14.2 R15.2 R25.2 R33.2 TP17.1 U2.2 U6.2 | length 9270.2
  L1-Top w8: Q1.2@915.4,872.82 938.46,872.82 950.27,861 v1(968.55,861) ; U6.2@1545.42,959.43 1545.42,985.02 1571.01,1010.61 R25.2@1571.01,1012.58
  L1-Top w10: R14.2@1225.53,1053.92 R15.2@1225.53,1014.55 1225.53,1012.58 1201.91,988.96 U2.2@1201.91,959.43 1201.91,927.48 1209.72,919.67 v1(1264.9,919.67) ; R1.2@1436.16,1198.78 1472.02,1198.78 1645.79,1025.01 1645.79,933.71 1631.35,919.27 v1(1608.41,919.27) ; U6.2@1545.42,959.43 1545.42,927.48 1553.23,919.67 C27.2@1608.41,919.67
  L1-Top w18: v1(1866.89,981.79) 2408.12,981.79 2663.38,1237.05 2663.38,1980.45 3067.17,2384.24 3260.93,2384.24 3282.52,2362.65 3282.52,2327.11 3308.1,2301.53 3393.41,2301.53 3416.68,2324.8 3416.68,2365.03 3438.68,2387.03 3697.35,2387.03 3835.16,2249.22 3835.16,1800.52 3619.31,1584.67 3619.31,1315.16
  L1-Top w22: 3619.31,1315.16 3588.57,1284.43 3588.57,1188.13 3756.74,1019.97 3860.46,1019.97 3912.93,967.49 3912.93,825.12 3930.12,807.93 3940.09,807.93 MC4.1@3956.68,791.34
  L1-Top w25: 3619.31,1315.16 4350.18,1315.16 4415.66,1249.69 4907.47,1249.69 4931.09,1226.06 MC1.1@4931.09,1173.82
  L4-BOT w18: TP17.1@809.29,1942.04 915.4,1835.94 915.4,914.15 v1(968.55,861) 1070.87,861 1129.53,919.67 v1(1264.9,919.67) 1265.1,919.47 1608.21,919.47 v1(1608.41,919.27) 1804.37,919.27 v1(1866.89,981.79)
VIO2: MC1.80 MC5.1 TP18.1 | length 9799
  L1-Top w25: MC1.80@3702.75,1416.73 3702.75,1570.24 v1(4460.38,2327.87) 4461.72,2327.87 5217.28,3083.43 v1(5217.57,3083.43) v1(5217.57,3120)
  L4-BOT w25: TP18.1@809.29,1698.66 693.95,1814 693.95,2721.21 759.39,2786.65 846.4,2786.65 920.71,2860.97 920.71,3352.86 1150.1,3582.25 1658.6,3582.25 1890.46,3350.39 2981.35,3350.39 3020.2,3311.54 3476.71,3311.54 v1(4460.38,2327.87) ; MC5.1@4665.35,4177.16 4665.35,4084.42 4728.1,4021.67 4973.32,4021.67 5217.57,3777.42 v1(5217.57,3120) v1(5217.57,3083.43)
VIO3: MC2.69 MC7.3 TP19.1 | length 5611.3
  L1-Top w25: MC2.69@3860.23,3457.28 v1(3860.23,3518.32) v1(3860.23,3551.13)
  L3-GND w25: TP19.1@809.29,1455.27 673.23,1591.34 673.23,2494.11 753.21,2574.1 831.83,2574.1 906.48,2648.74 906.48,3317.29 1095.18,3506 v1(1297.93,3506) 1706.44,3506 1854.17,3358.27 3713.48,3358.27 3764.66,3409.45 3860.23,3505.01 v1(3860.23,3551.13)
  L4-BOT w25: v1(1297.93,3506) 1297.93,3390.56 MC7.3@1397.63,3290.86
VIO_PG: Q1.3 R31.1 R32.2 U5.3 | length 1653.1
  L1-Top w7: R31.1@929.18,951.56 929.18,931.26 915.4,917.49 Q1.3@915.4,898.41 916.38,897.42 967.56,897.42 R32.2@968.55,896.44 1000.45,896.44 1009.51,887.38 v1(1009.51,821.42) ; v1(2011.03,421.26) 2024.7,407.59 2116.77,407.59 2127.94,396.41 U5.3@2127.94,375.2
  L4-BOT w7: v1(1009.51,821.42) 1009.51,777.89 1137.95,649.45 1484,649.45 1548.58,714.03 1777.83,714.03 2011.03,480.83 v1(2011.03,421.26)
VREF1: MC1.4 MC4.2 | length 1926.4
  L1-Top w18: v1(3695.42,1348.15) 4375.02,1348.15 4435.76,1287.4 4857.76,1287.4 4899.6,1329.24 MC1.4@4899.6,1416.73
  L4-BOT w18: v1(3695.42,1348.15) 3695.42,1121.1 3909.44,907.08 3932.38,884.14 3933.64,884.14 3947.71,870.08 MC4.2@3956.68,870.08
VREFP: J2.8 MC2.79 R5.2 R6.2 | length 2285.6
  L1-Top w8: v1(2598.88,3401.4) 2616.42,3383.86 3687.01,3383.86 3702.75,3399.6 MC2.79@3702.75,3457.28
  L1-Top w10: R5.2@1680.8,3591.06 1680.8,3589.09 1734.8,3535.1 1735.02,3535.1 1747.73,3522.38 R6.2@1747.73,3520.41 1747.73,3518.44 1760.45,3505.73 1762.42,3505.73 1796.57,3471.58 1980.81,3471.58 J2.8@2063.92,3554.69
  L4-BOT w7.5: J2.8@2063.92,3554.69 2063.92,3485.4 2148.76,3400.56 2598.03,3400.56 v1(2598.88,3401.4)
XADC_VN_C: J2.3 MC2.80 | length 1876.1
  L1-Top w5.25: v1(2608.88,3500.37) 2611.05,3502.55 2621.48,3502.55 2943.74,3824.8 3364.17,3824.8 3533.69,3655.28 3705.98,3655.28 3712.87,3662.17 3712.87,3671.2 3709.8,3674.28 3709.18,3674.28 3702.75,3680.71 MC2.80@3702.75,3700.2
  L4-BOT w5.25: J2.3@2263.92,3654.69 2263.92,3661.71 2311.24,3709.03 2422.36,3709.03 2449.7,3681.68 2449.7,3608.37 2575.79,3482.28 2601.22,3482.28 2606.7,3487.77 2606.7,3498.2 v1(2608.88,3500.37)
XADC_VP_C: J2.1 MC2.78 | length 1785.9
  L1-Top w5.25: v1(2627.26,3481.99) 2629.44,3484.16 2629.44,3494.59 2948.4,3813.55 3359.51,3813.55 3529.03,3644.03 3710.64,3644.03 3724.12,3657.51 3724.12,3671.2 3727.2,3674.28 3727.81,3674.28 3734.24,3680.71 MC2.78@3734.24,3700.2
  L4-BOT w5.25: J2.1@2363.92,3654.69 2407.01,3697.78 2417.7,3697.78 2438.45,3677.02 2438.45,3603.71 2571.13,3471.03 2605.88,3471.03 2614.66,3479.82 2625.09,3479.82 v1(2627.26,3481.99)
pads on no net: FID1.FID? FID2.FID? FID3.FID? FID4.FID? J1.A03 J1.A04 J1.B03 J1.B04 J2.4 J2.5 J2.6 J3.12 J3.14 J4.3 J5.0 J6.A5 J6.A6 J6.A7 J6.A8 J6.A19 J6.A32 J6.A33 J6.B9 J6.B12 J6.B30 MC1.81 MC1.82 MC2.81 MC2.82 MC3.MH MC7.13 MC7.15 MC7.17 MH1.1 MH2.1 MH3.1 MH4.1 U6.4 U6.5

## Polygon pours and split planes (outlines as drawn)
+12V_PCIE_C on L1-Top "+12V_PCIE_C_L01_P089" (solid, pour order 89): 1791.45,351.2 1791.45,242.76 1891.94,242.76 1891.94,322.29 1863.03,351.2
+VDCIN on L1-Top "+VDCIN_L01_P088" (solid, pour order 88): 904.18,3929.12 860.07,3885.01 860.07,3571.6 828.5,3540.02 627.23,3540.02 606.3,3560.95 606.3,3764.76 539.94,3764.76 539.94,4003.98 718.23,4182.28 1384.38,4182.28 1445.44,4121.22 1826.39,4121.22 1858.26,4089.34 1858.26,3950.7 1836.68,3929.12
+VDCIN on L4-BOT "+VDCIN_L04_P087" (solid, pour order 87): 2659.75,3740.16 2773.93,3625.98 3060.18,3339.73 3487.04,3339.73 3913.39,2913.39 4992.13,2913.39 5112.2,3033.46 5112.2,3740.16 4990.15,3862.2 4889.76,3862.2 4889.76,3244.09 4850.39,3204.72 4153.77,3204.72 3515.97,3842.52 3389.63,3842.52 3251.83,3980.31 3007.87,3980.32 2854.32,4133.87 2854.32,4492.13 754.32,4492.12 539.94,4277.74 539.94,3572.32 572.24,3540.02 809.29,3540.02 860.07,3590.8 860.07,3824.39 935.12,3899.45 1325.01,3899.45 1484.3,3740.16
DGND on L2-GND "DGND_L02_P090" (solid, pour order 90): 590.54,177.16 590.54,501.97 1312.98,501.97 1312.98,177.16 1627.94,177.16 1627.94,430.12 cw(c1699.8,430.12) 1771.65,430.12 1771.65,225.39 2212.59,225.39 2212.59,293.31 cw(c2249.99,293.31) 2287.39,293.31 2287.39,225.39 3791.33,225.39 3791.33,501.97 6600.39,501.97 6600.39,4492.13 -0.01,4492.13 -0.01,177.16
DGND on L3-GND "DGND_L03_P091" (solid, pour order 91): 590.54,177.16 590.54,501.97 1312.98,501.97 1312.98,177.16 1627.94,177.16 1627.94,430.12 cw(c1699.8,430.12) 1771.65,430.12 1771.65,225.38 2212.59,225.38 2212.59,293.31 cw(c2249.99,293.31) 2287.39,293.31 2287.39,225.38 3791.33,225.38 3791.33,501.97 6600.39,501.97 6600.39,4492.13 -0.01,4492.13 -0.01,177.16

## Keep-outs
L1-Top:
  rectangle: 3791.33,501.97 6600.39,541.34
  rectangle: -0.01,3531.5 499.99,3940.94
L4-BOT:
  rectangle: -0.01,905.51 199.99,3531.5
  rectangle: -0.01,3531.5 499.99,3940.94
  rectangle: 3791.33,501.97 6600.39,541.34
Keep-Out Layer:
  rectangle: 1312.98,177.16 1627.94,312.99

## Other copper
L1-Top:
  region net DGND: 3308.21,2798.42 3364.95,2798.42 3364.95,2651.73 3343.09,2651.73 3343.09,2613.38 3308.21,2613.38
  region net +1.2V_DDR: 3445.46,3090.55 3502.55,3090.55 3502.55,3126.26 3493.26,3135.55 3454.86,3135.55 3445.46,3126.15
  region net +VDCIN: 4890.54,3671.65 4952.72,3671.65 4991.26,3710.19 4991.26,3831.22 4960.28,3862.2 4890.54,3862.2
  region net +VDCIN: 4890.54,3485.83 4950.1,3485.83 5009.66,3426.27 5009.66,3295.27 4890.54,3295.27
  region net DGND: 644.87,3278.21 806.28,3278.21 806.28,3502.95 644.87,3502.95
  region net DGND: 3339.76,3212.99 3391.72,3212.99 3391.72,3112.99 3364.95,3112.99 3339.76,3112.99
  region net DGND: 3308.21,2590.55 3364.3,2590.55 3391.72,2563.13 3391.72,2448.42 3364.95,2448.42 3308.21,2448.42
  region net DGND: 3308.21,2425.59 3391.72,2425.59 3391.72,2325.59 3364.95,2325.59 3308.21,2325.59
  region net DGND: 3308.21,1761.02 3391.72,1761.02 3391.72,1661.02 3364.95,1661.02 3308.21,1661.02
  region net DGND: 3308.21,2261.02 3391.72,2261.02 3391.72,2075.98 3364.95,2075.98 3308.21,2075.98
  region net DGND: 3280,3048.42 3391.72,3048.42 3391.72,2863.38 3364.95,2863.38 3280,2863.38
  region net DGND: 3308.21,2011.02 3391.72,2011.02 3391.72,1825.98 3364.95,1825.98 3308.21,1825.98

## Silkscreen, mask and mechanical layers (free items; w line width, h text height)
Top Overlay:
  circle w22: c1757.02,3916.26 r11
  rectangle: 5585.06,594.49 6246.06,909.45
  lines w10: 6579.87,1059.05 2663.38,1059.05 2663.38,3814.96 6579.87,3814.96
  lines w15.75: 1669.02,3916.26 1717.02,3916.26 ; 1757.02,3916.26 1819.02,3916.26 ; 1770.7,3878.68 cw(c1757.02,3916.26) 1770.7,3953.85
  text "7.5-15 VDC" at 1411.25,4476.83 h45 r270
  text "DGND" at 2760.12,4395.29 h30
  text "DGND" at 4492.4,4395.29 h30
  text "1.8V" at 2166.84,4347.8 h55 r270
  text "TMS" at 2251.86,4343.88 h55 r270
  text "TDO" at 2401.47,4344.33 h55 r270
  text "TCK" at 2326.67,4343.44 h55 r270
  text "TDI" at 2484.15,4318.53 h55 r270
  text "PWR" at 442.52,4309.78 h50 r90
  text "+" at 1832.02,3955.26 h70 r270
  text "GNDADC" at 2042.98,3926.92 h50 r270
  text "JTAG" at 2346.6,3893.7 h80
  text "-" at 1577.03,3881.27 h70
  text "VN" at 2242.98,3793.81 h50 r270
  text "VP" at 2342.98,3792.87 h50 r270
  text "SYSMON" at 2501.56,3756.75 h80 r270
  text "VREFP" at 2037.01,3491.7 h50 r270
  text "VCCADC" at 2337.01,3491.7 h50 r270
  text "DGND" at 1298.35,3401.72 h30 r270
  text "'.Part_Number' / '.PCB_Revision'XX" at 3129.93,711.52 h40
  text "DGND" at 3924.57,692.06 h30
Top Solder:
  rectangle: 1312.98,177.16 1627.94,312.99
Solder Side:
  rectangle: 1312.98,177.16 1627.94,312.99
Dimensions:
  rectangle: 1781.49,9.84 3781.49,56.93
  lines w1: 4526.47,-267.17 4547.19,-321.84 4567.68,-321.84 4588.52,-266.87 ; 4526.83,-267.19 4526.83,28.16
  lines w2: 4588.43,-266.84 4588.43,-25.42 ; 4638.85,-134.01 4687.73,-5.23
  lines w10: 3781.49,9.84 4220.47,-515.75 ; 3781.49,56.93 4343.78,350.39 ; 5349.4,-145.34 cw(c4724.4,-145.34) 5349.4,-143.92
  text ":::" at 4780.04,4566.93 h50 r180
  text ":::" at 465.27,4551.18 h50 r180
  text ":::" at 6687,3915.56 h50 r90
  text ":::" at -43.31,3307.09 h50 r90
  text ":::" at 6685.03,1080.71 h50 r90
  text ":::" at -43.31,969.27 h50 r90
  text "EDGE BEVEL" at 4455.01,340.55 h50
  text "ACROSS PADS" at 4586.74,-588.49 h50
  text "ALL UNITS IN MILLIMETERS UNLESS OTHERWISE SPECIFIED" at 708.66,-629.92 h60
